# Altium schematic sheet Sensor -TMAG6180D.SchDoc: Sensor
size A4; Date: Not shown in title block; ApprovedBy: Hely Zhang; CheckedBy: Not shown in title block; Author: Not shown in title block; CompanyName: Not shown in title block; DrawnBy: Hely Zhang; Engineer: Not shown in title block; Organization: Not shown in title block; Address1: Not shown in title block; Address2: Not shown in title block; Address3: Not shown in title block; Address4: Not shown in title block; DocumentNumber: 1; Revision: Use project parameter SCH_Rev; SheetNumber: 9; SheetTotal: 14; PageSetup: Record=PageOptions¦CenterHorizontal=True¦CenterVertical=True¦PrintScale=0.93¦XCorrection=1.00¦YCorrection=1.00¦PrintKind=0¦BorderSize=5000000¦LeftOffset=0¦BottomOffset=0¦Orientation=2¦PaperLength=1000¦PaperWidth=1000¦Scale=100¦PaperSource=15¦PrintQuality=600¦MediaType=1¦DitherType=10¦PaperKind=Letter¦PrintScaleMode=1
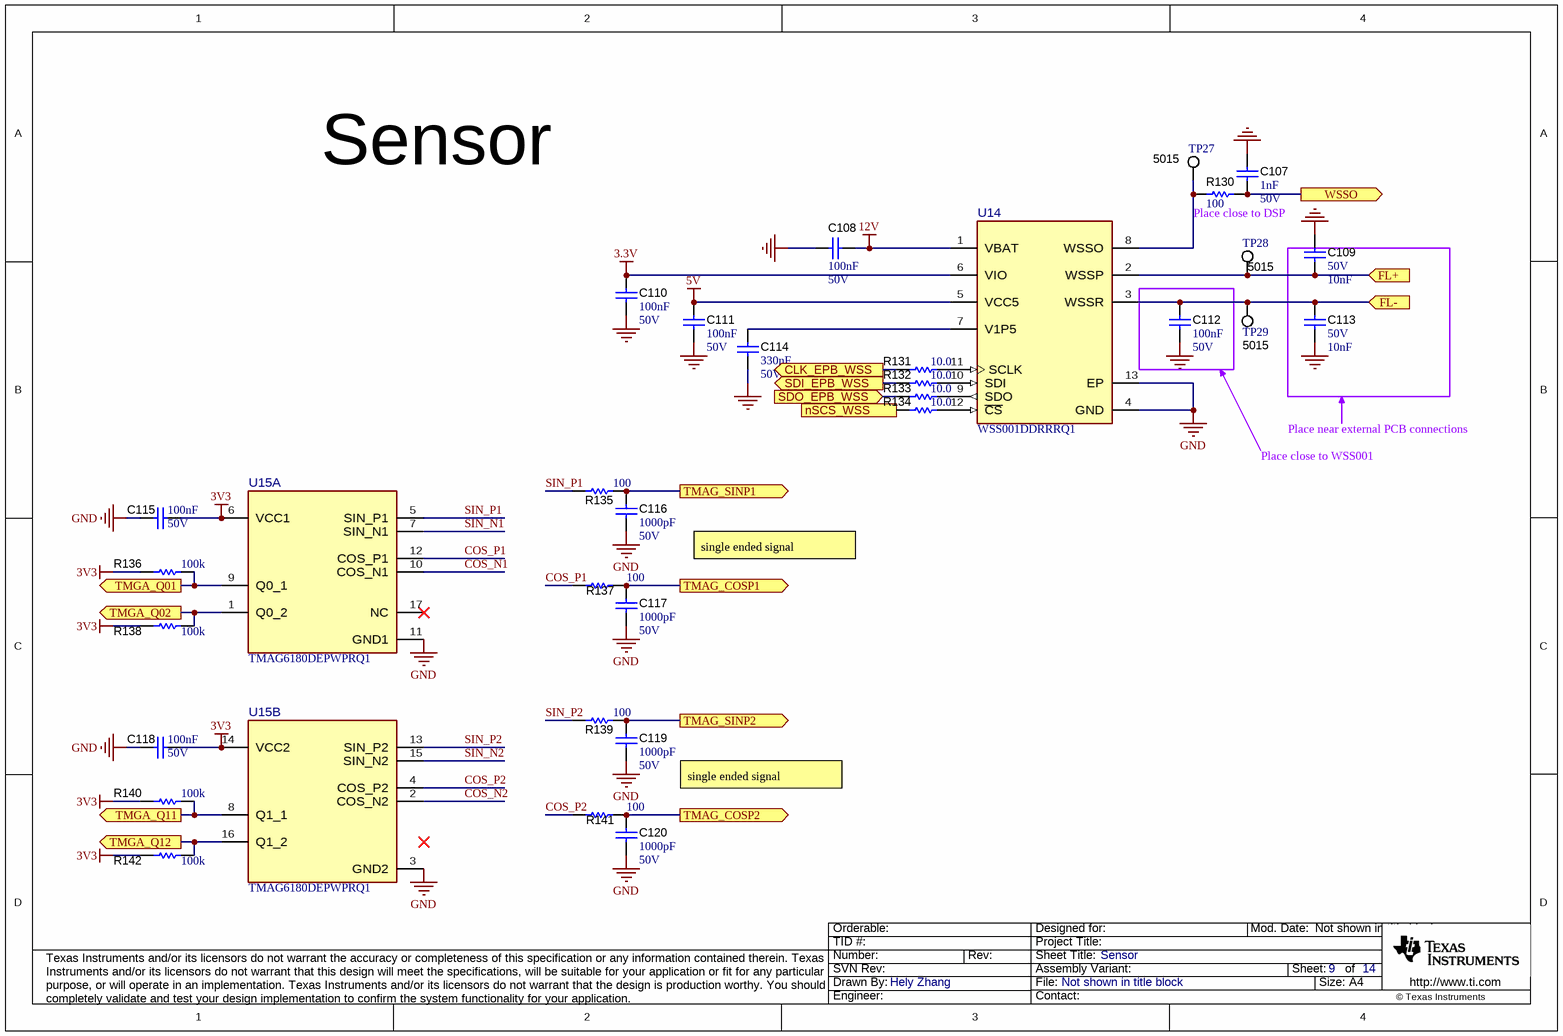
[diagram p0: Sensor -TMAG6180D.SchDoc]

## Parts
C107  Cap_F: 1nF  VDC_V: 50V  [0603]  (hidden comment: GRM188R71H102KA01D)
C108  Cap_F: 100nF  VDC_V: 50V  [0603]  (hidden comment: 885012206095)
C109  VDC_V: 50V  Cap_F: 10nF  [0603]  (hidden comment: 885012206089)
C110  Cap_F: 100nF  VDC_V: 50V  [0603]  (hidden comment: 885012206095)
C111  Cap_F: 100nF  VDC_V: 50V  [0603]  (hidden comment: 885012206095)
C112  Cap_F: 100nF  VDC_V: 50V  [0603]  (hidden comment: 885012206095)
C113  VDC_V: 50V  Cap_F: 10nF  [0603]  (hidden comment: 885012206089)
C114  Cap_F: 330nF  VDC_V: 50V  [0603]  (hidden comment: CGA3E3X7R1H334K080AB)
C115  Cap_F: 100nF  VDC_V: 50V  [0603]  (hidden comment: GCM188R71H104KA57D)
C116  ValueDisplayed: 1000pF  VDC_V: 50V  [0402]  (hidden comment: CGA2B2X8R1H102K050BA)
C117  ValueDisplayed: 1000pF  VDC_V: 50V  [0402]  (hidden comment: CGA2B2X8R1H102K050BA)
C118  Cap_F: 100nF  VDC_V: 50V  [0603]  (hidden comment: GCM188R71H104KA57D)
C119  ValueDisplayed: 1000pF  VDC_V: 50V  [0402]  (hidden comment: CGA2B2X8R1H102K050BA)
C120  ValueDisplayed: 1000pF  VDC_V: 50V  [0402]  (hidden comment: CGA2B2X8R1H102K050BA)
R130  ValueDisplayed: 100  [0603]  (hidden comment: RC0603FR-07100RL)
R131  ValueDisplayed: 10.0  [0603]  (hidden comment: RC0603FR-0710RL)
R132  ValueDisplayed: 10.0  [0603]  (hidden comment: RC0603FR-0710RL)
R133  ValueDisplayed: 10.0  [0603]  (hidden comment: RC0603FR-0710RL)
R134  ValueDisplayed: 10.0  [0603]  (hidden comment: RC0603FR-0710RL)
R135  value 100  [0402]  (hidden comment: RMCF0402JT100R)
R136  ValueDisplayed: 100k  [0201]  (hidden comment: RC0201DR-07100KL)
R137  ValueDisplayed: 100  [0402]  (hidden comment: RMCF0402JT100R)
R138  ValueDisplayed: 100k  [0201]  (hidden comment: RC0201DR-07100KL)
R139  value 100  [0402]  (hidden comment: RMCF0402JT100R)
R140  ValueDisplayed: 100k  [0201]  (hidden comment: RC0201DR-07100KL)
R141  ValueDisplayed: 100  [0402]  (hidden comment: RMCF0402JT100R)
R142  ValueDisplayed: 100k  [0201]  (hidden comment: RC0201DR-07100KL)
TP27  5015  [Testpoint_Keystone_Miniature]
TP28  5015  [Testpoint_Keystone_Miniature]
TP29  5015  [Testpoint_Keystone_Miniature]
U14  WSS001DDRRRQ1  [DRR0012E-MFG]
U15  TMAG6180DEPWPRQ1  [PWP0016R-MFG]  (parts A,B of 2)

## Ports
CLK_EPB_WSS (out), FL+ (in), FL- (in), nSCS_WSS (in), SDI_EPB_WSS (out), SDO_EPB_WSS (in), TMAG_COSP1 (out), TMAG_COSP2 (out), TMAG_SINP1 (out), TMAG_SINP2 (out), TMGA_Q01 (out), TMGA_Q02 (out), TMGA_Q11 (out), TMGA_Q12 (out), WSSO (out)

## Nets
3.3V: C110.1 U14.6(VIO)
3V3: C115.1 C118.1 R136.2 R138.2 R140.2 R142.2 U15.6(VCC1) U15.14(VCC2)
5V: C111.1 U14.5(VCC5)
12V: C108.2 U14.1(VBAT)
GND: C107.1 C108.1 C109.1 C110.2 C111.2 C112.2 C113.2 C114.2 C115.2 C116.2 C117.2 C118.2 C119.2 C120.2 U14.4(GND) U14.13(EP) U15.3(GND2) U15.11(GND1)
CLK_EPB_WSS: R131.1 ; port CLK_EPB_WSS
COS_N1: U15.10(COS_N1)
COS_N2: U15.2(COS_N2)
COS_P1: R137.1 U15.12(COS_P1)
COS_P2: R141.1 U15.4(COS_P2)
FL+: C109.2 TP28.1 U14.2(WSSP) ; port FL+
FL-: C112.1 C113.1 TP29.1 U14.3(WSSR) ; port FL-
nSCS_WSS: R134.1 ; port nSCS_WSS
SDI_EPB_WSS: R132.1 ; port SDI_EPB_WSS
SDO_EPB_WSS: R133.1 ; port SDO_EPB_WSS
SIN_N1: U15.7(SIN_N1)
SIN_N2: U15.15(SIN_N2)
SIN_P1: R135.1 U15.5(SIN_P1)
SIN_P2: R139.1 U15.13(SIN_P2)
TMAG_COSP1: C117.1 R137.2 ; port TMAG_COSP1
TMAG_COSP2: C120.1 R141.2 ; port TMAG_COSP2
TMAG_SINP1: C116.1 R135.2 ; port TMAG_SINP1
TMAG_SINP2: C119.1 R139.2 ; port TMAG_SINP2
TMGA_Q01: R136.1 U15.9(Q0_1) ; port TMGA_Q01
TMGA_Q02: R138.1 U15.1(Q0_2) ; port TMGA_Q02
TMGA_Q11: R140.1 U15.8(Q1_1) ; port TMGA_Q11
TMGA_Q12: R142.1 U15.16(Q1_2) ; port TMGA_Q12
WSSO: C107.2 R130.2 ; port WSSO
NetC114_1: C114.1 U14.7(V1P5)
NetR130_1: R130.1 TP27.1 U14.8(WSSO)
NetR131_2: R131.2 U14.11(SCLK)
NetR132_2: R132.2 U14.10(SDI)
NetR133_2: R133.2 U14.9(SDO)
NetR134_2: R134.2 U14.12(~{CS})

Not connected (* = marked no-connect by the designer): U15 17(NC)*

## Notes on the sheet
- Sensor
- (near R130) Place close to DSP
- Place near external PCB connections
- Place close to WSS001
- single ended signal

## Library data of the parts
C107 = CMP-0007432-1: CAP, CERM, 1000 pF, 50 V, +/- 10%, X7R, 0603; Manufacturer: MuRata; TaMin_C: -55°C; Polarized: N; SizeAreaWB_mm2: 4.68; Value1: Unknown; U/M: EA; Value: 1000pF; TaMax_C: 125°C; SizeZ_mm: 1; SizeX_mm: 1.6; SizeY_mm: 0.8; SizeArea_mm2: 1.28; AEC Category: Q200
C108 C110-C112 = CMP-0006837-1: CAP, CERM, 0.1 uF, 50 V, +/- 10%, X7R, 0603; Manufacturer: Wurth Elektronik; TaMin_C: -55°C; Polarized: N; SizeAreaWB_mm2: 4.68; Value1: Unknown; U/M: EA; Value: 0.1uF; TaMax_C: 125°C; SizeZ_mm: 1; SizeX_mm: 1.6; SizeY_mm: 0.8; SizeArea_mm2: 1.28; AEC Category: Q200
C109 C113 = CMP-0750039-1: CAP, CERM, 0.01 µF, 50 V,+/- 10%, X7R, 0603; Manufacturer: Wurth Elektronik; Polarized: N; AEC Category: Q200; TaMax_C: 125°C; SizeAreaWB_mm2: 4.68; Value: 0.01uF; SizeArea_mm2: 1.28; SizeY_mm: 0.8; SizeZ_mm: 1; ValueDisplayed: 0.01µF; SizeX_mm: 1.6; U/M: EA; TaMin_C: -55°C
C114 = CMP-0007095-1: CAP, CERM, 0.33 uF, 50 V, +/- 10%, X7R, AEC-Q200 Grade 1, 0603; Manufacturer: TDK; TaMin_C: -55°C; ESR_ohm: 15.84m; Polarized: N; SizeAreaWB_mm2: 4.68; Value1: 0.01584 ohm; U/M: EA; Value: 0.33uF; TaMax_C: 125°C; SizeZ_mm: 1; SizeX_mm: 1.6; SizeY_mm: 0.8; SizeArea_mm2: 1.28; AEC Qualified: Y; IRMS_A: 1.3135A; AEC Category: Q200
C115 C118 = CMP-0007144-1: CAP, CERM, 0.1 uF, 50 V, +/- 10%, X7R, 0603; Manufacturer: MuRata; TaMin_C: -55°C; ESR_ohm: 20m; Polarized: N; SizeAreaWB_mm2: 4.68; Value1: 0.02 ohm; U/M: EA; Value: 0.1uF; TaMax_C: 125°C; SizeZ_mm: 1; SizeX_mm: 1.6; SizeY_mm: 0.8; SizeArea_mm2: 1.28; IRMS_A: 1.84A; AEC Category: Q200
C116 C117 C119 C120 = CMP-0860997-1: CAP, CERM, 1000 pF, 50 V,+/- 10%, X8R, AEC-Q200 Grade 0, 0402; Manufacturer: TDK; SizeArea_mm2: 0.5; U/M: EA; SizeX_mm: 1; Polarized: N; AEC Grade: 0; AEC Qualified: Y; TaMin_C: -55°C; Value: 1000pF; TaMax_C: 150°C; SizeZ_mm: 0.6; Cap_F: 1nF; SizeAreaWB_mm2: 3; AEC Category: Q200
R130 = CMP-0022736-4: RES, 100, 1%, 0.1 W, 0603; Manufacturer: Yageo; Power_W: 100mW; TempCo: 100 ppm/C; Value_Code: 100R; Value: 100; EIA_Code: E96; SizeX_mm: 1.6; SizeY_mm: 0.8; SizeZ_mm: 1; Value2: 0.1W; SizeArea_mm2: 1.28; AEC Qualified: N; VDC_V: 75V; AEC Category: Q200; SizeAreaWB_mm2: 4.68
R131-R134 = CMP-0022751-4: RES, 10.0, 1%, 0.1 W, 0603; Manufacturer: Yageo; Power_W: 100mW; TempCo: 100 ppm/C; Value_Code: 10R0; Value: 10.0; EIA_Code: E96; Res_ohm: 10; SizeX_mm: 1.6; SizeY_mm: 0.8; SizeZ_mm: 1; Value2: 0.1W; SizeArea_mm2: 1.28; AEC Qualified: N; VDC_V: 75V; AEC Category: Q200; SizeAreaWB_mm2: 4.68
R135 R139 = CMP-0026763-1: RES, 100, 1%, 0.063 W, AEC-Q200 Grade 0, 0402; Manufacturer: Stackpole Electronics Inc; Power_W: 63mW; TempCo: 100 ppm/C; Value_Code: 100R; U/M: EA; EIA_Code: E96; SizeX_mm: 1; SizeY_mm: 0.5; SizeZ_mm: 0.6; Value2: 0.063W; AEC Qualified: Y; AEC Grade: 0; AEC Category: Q200
R136 R138 R140 R142 = CMP-0028132-1: RES, 100 k, 0.5%, 0.05 W, 0201; Manufacturer: Yageo America; Power_W: 50mW; TempCo: 200 ppm/C; U/M: EA; Value: 100k; EIA_Code: E192; SizeX_mm: 0.6; SizeY_mm: 0.3; SizeZ_mm: 0.26; Value2: 0.05W; SizeArea_mm2: 0.18; AEC Qualified: N; VDC_V: 25V; AEC Category: Q200
R137 R141 = CMP-0026763-1: RES, 100, 1%, 0.063 W, AEC-Q200 Grade 0, 0402; Manufacturer: Stackpole Electronics Inc; Power_W: 63mW; TempCo: 100 ppm/C; Value_Code: 100R; U/M: EA; Value: 100; EIA_Code: E96; SizeX_mm: 1; SizeY_mm: 0.5; SizeZ_mm: 0.6; Value2: 0.063W; AEC Qualified: Y; AEC Grade: 0; AEC Category: Q200
TP27-TP29 = CMP-0055152-2: Test Point, Miniature, SMT; Manufacturer: Keystone Electronics; CT: TRUE; Green_Lifecycle: Active; Green_REACh: Passed; CNHeader: FALSE
U14 = CMP-0123269-1: Manufacturer: Texas Instruments; SizeZ_mm: 0.8mm; Standoff Height: 0mm
U15 = CMP-0124682-1: Manufacturer: Texas Instruments; SizeZ_mm: 1.2mm; Standoff Height: 0.05mm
